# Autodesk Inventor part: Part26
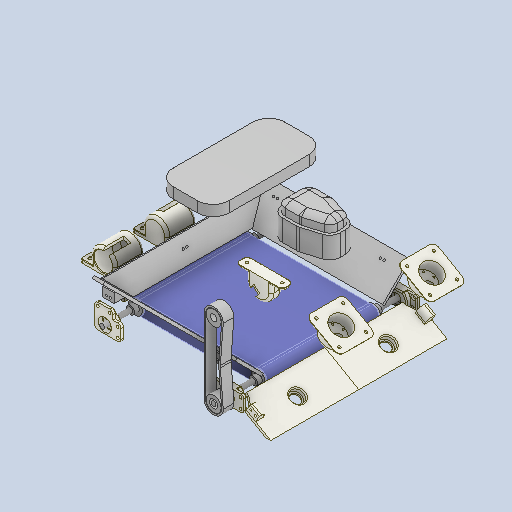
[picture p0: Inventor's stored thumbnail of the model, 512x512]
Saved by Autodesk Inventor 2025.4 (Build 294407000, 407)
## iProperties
Created: 2026-06
Part Number: Part26
Material: Generic
Document SubType Name: Modeling
Designer: AdminForWorker
Density: 1 g/cm^3
Appearance: Default
Author: AdminForWorker
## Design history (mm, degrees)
feature "Roller Avant" [Body]
feature "Roller Avant (1)" [Body]
feature "Enveloppe avant" [Body]
feature "Enveloppe avant (1)" [Body]
feature "Enveloppe Haut" [Body]
feature "Env roul1" [Body]
feature "Env roul1 (2)" [Body]
feature "Body179"
feature "Body41"
feature "Body42"
feature "Body178"
feature "Frame (1)" [Body]
feature "Frame (2)" [Body]
feature "Env Tapis Arriere_D" [Body]
feature "Env Tapis Arriere_G" [Body]
feature "Env_mot_G" [Body]
feature "Env_mot_D" [Body]
feature "RampeG" [Body]
feature "Calle_Rampe" [Body]
feature "Calle_Rampe2" [Body]
feature "Calle_murD" [Body]
feature "Calle_murG" [Body]
feature "RampeD" [Body]
feature "BloqueBloc" [Body]
feature "Equerre45" [Body]
feature "Equerre45 (1)" [Body]
feature "Equerre45 (2)" [Body]
feature "Equerre45 (1) (1)" [Body]
feature "Equerre70" [Body]
body "Solid1"
body "Solid2"
body "Solid3"
body "Solid4"
body "Solid5"
body "Solid6"
body "Solid7"
body "Solid8"
body "Solid9"
body "Solid10"
body "Solid11"
body "Solid12"
body "Solid13"
body "Solid14"
body "Solid15"
body "Solid16"
body "Solid17"
body "Solid18"
body "Solid19"
body "Solid20"
body "Solid21"
body "Solid22"
body "Solid23"
body "Solid24"
body "Solid25"
body "Solid26"
body "Solid27"
body "Solid28"
body "Solid29"
